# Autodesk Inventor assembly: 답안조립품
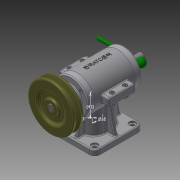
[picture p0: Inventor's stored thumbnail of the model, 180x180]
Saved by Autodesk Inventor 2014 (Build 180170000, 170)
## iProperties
Created: 2015-12
Part Number: 답안조립품
Document SubType Name: Assembly
Designer: test_01
Mass: 1497.03 g
Surface Area: 1487.05 cm^2
Volume: 469.721 cm^3
Density: 3.18707 g/cm^3
Author: test_01
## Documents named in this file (19)
- C:\Users\test_01\Desktop\351207V1029\351207V1029\답안조립품.iam
- C:\Users\test_01\Desktop\351207V1029\351207V1029\본체.ipt
- C:\Users\test_01\Desktop\351207V1029\351207V1029\본체커버.ipt
- C:\Users\test_01\Desktop\351207V1029\351207V1029\뒤커버.ipt
- C:\Users\test_01\Desktop\351207V1029\351207V1029\베어링 6202.ipt
- C:\Users\test_01\Desktop\351207V1029\351207V1029\오일실 12 22 7.ipt
- C:\Users\test_01\Desktop\351207V1029\351207V1029\편심축.ipt
- C:\Users\test_01\Desktop\351207V1029\351207V1029\베어링 6201.ipt
- C:\Users\test_01\Desktop\351207V1029\351207V1029\앞커버.ipt
- C:\Users\test_01\Desktop\351207V1029\351207V1029\멈춤나사 M3x8.ipt
- C:\Users\test_01\Desktop\351207V1029\351207V1029\키 4 x 4 x 18.ipt
- C:\Users\test_01\Desktop\351207V1029\351207V1029\V-벨트풀리.ipt
- C:\Users\test_01\Desktop\351207V1029\351207V1029\볼트 M3x0.5x8.ipt
- C:\Users\test_01\Desktop\351207V1029\351207V1029\볼트 M4 x 16.ipt
- C:\Users\test_01\Desktop\351207V1029\351207V1029\너트 M4.ipt
- C:\Users\test_01\Desktop\351207V1029\351207V1029\와셔 ST 4-100.ipt
- C:\Users\test_01\Desktop\351207V1029\351207V1029\슬라이드.ipt
- C:\Users\test_01\Desktop\351207V1029\351207V1029\가변스프링.ipt
- C:\Users\test_01\Desktop\351207V1029\351207V1029\레바.ipt
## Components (14 placed, 5 different names)
1. V-벨트풀리:1
2. ISO 4762 M4 x 16:1
3. ISO 4762 M4 x 16:2
4. ISO 4762 M4 x 16:3
5. ISO 4762 M4 x 16:4
6. ISO 4032 M4:1
7. ISO 7091 ST 4 - 100 HV:1
8. ISO 4032 M4:2
9. ISO 7091 ST 4 - 100 HV:2
10. ISO 4032 M4:3
11. ISO 7091 ST 4 - 100 HV:3
12. ISO 4032 M4:4
13. ISO 7091 ST 4 - 100 HV:4
14. 가변스프링:1
